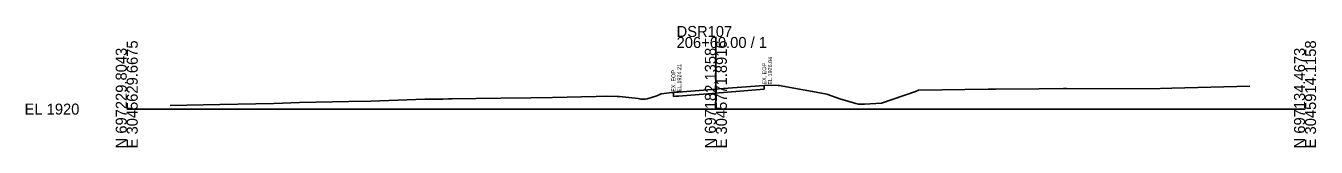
# Model space of a CAD drawing. Extents: x -26 to 19003, y -31 to 24541.
# Drawn here: x 1974.3 to 2302.8, y 13490.3 to 13521.2 of the extents above; entities that cross this region are included whole.
import ezdxf

# ---------------------------------------------------------------- set-up
doc = ezdxf.new("R2010")
doc.units = 0
for name, color, linetype in [('DESIGN - SHEET - Light Grid', 7, 'Continuous'), ('SURVEY - GROUND - Existing Pavement Layer', 7, 'Continuous'), ('SURVEY - GROUND - Existing Pavement Text', 7, 'Continuous'), ('SURVEY - GROUND - Top of Ground', 7, 'Continuous')]:
    doc.layers.add(name, color=color, linetype=linetype)

msp = doc.modelspace()

# ---------------------------------------------------------------- linework, layer by layer
at = {"layer": 'DESIGN - SHEET - Light Grid'}
for p, q in [((2150, 13500), (2150, 13518.36)), ((2000, 13500), (2150, 13500)), ((2150, 13500), (2300, 13500))]:
    msp.add_line(p, q, dxfattribs=at)
at = {"layer": 'SURVEY - GROUND - Existing Pavement Layer'}
for p, q in [((2162.31, 13506.04), (2162.31, 13505.04)), ((2139.18, 13503.21), (2139.18, 13504.21)), ((2139.18, 13503.21), (2139.79, 13503.28)), ((2139.79, 13503.28), (2140.48, 13503.33)), ((2140.48, 13503.33), (2150, 13504.06)), ((2150, 13504.06), (2150.8, 13504.12)), ((2150.8, 13504.12), (2151.91, 13504.21)), ((2151.91, 13504.21), (2162.31, 13505.04))]:
    msp.add_line(p, q, dxfattribs=at)
at = {"layer": 'SURVEY - GROUND - Top of Ground'}
msp.add_lwpolyline([(2011.04, 13500.9), (2023.69, 13501.15), (2037.46, 13501.45), (2043.96, 13501.71), (2056.55, 13501.93), (2062.17, 13502.05), (2075.92, 13502.53), (2078.22, 13502.52), (2080.59, 13502.57), (2081.9, 13502.59), (2082.83, 13502.61), (2088.95, 13502.7), (2095.26, 13502.79), (2102.92, 13502.88), (2108.41, 13502.94), (2119.49, 13503.2), (2122.24, 13503.29), (2124.9, 13503.25), (2125.48, 13503.25), (2130.21, 13502.67), (2130.91, 13502.52), (2132.01, 13502.56), (2132.49, 13502.6), (2134.96, 13503.34), (2136.11, 13503.88), (2138.14, 13504.1), (2139.18, 13504.21), (2139.79, 13504.28), (2140.48, 13504.33), (2150, 13505.06), (2150.8, 13505.12), (2151.91, 13505.21), (2162.31, 13506.04), (2163.39, 13506.12), (2165.87, 13506.05), (2166.18, 13506.04), (2167.08, 13505.85), (2176.48, 13504.12), (2178.26, 13503.78), (2181.58, 13502.63), (2185.59, 13501.41), (2186.3, 13501.22), (2187.87, 13501.28), (2192.14, 13501.54), (2200.85, 13504.48), (2201.57, 13504.79), (2219.31, 13505.06), (2221.25, 13505.1), (2232.24, 13505.19), (2238.53, 13505.24), (2239.31, 13505.26), (2260.2, 13505.2), (2266.11, 13505.35), (2285.98, 13505.81)], dxfattribs=at)

# ---------------------------------------------------------------- texts
at = {"layer": 'DESIGN - SHEET - Light Grid'}
for s, p in [('DSR107', (2140, 13518.36)), ('206+60.00 / 1', (2140, 13515.56)), ('EL 1920', (1974, 13498.6))]:
    msp.add_text(s, height=2.8, dxfattribs=at).set_placement(p)
for s, p in [('E 3045629.6675', (2002.8, 13490)), ('E 3045771.8916', (2152.8, 13490)), ('E 3045914.1158', (2302.8, 13490)), ('N 697229.8043', (2000, 13490)), ('N 697182.1358', (2150, 13490)), ('N 697134.4673', (2300, 13490))]:
    msp.add_text(s, height=2.8, rotation=90, dxfattribs=at).set_placement(p)
at = {"layer": 'SURVEY - GROUND - Existing Pavement Text'}
for s, p in [('EL.1926.04', (2164.31, 13506.24)), ('EX. EOP', (2139.68, 13504.41)), ('EL.1924.21', (2141.18, 13504.41)), ('EX. EOP', (2162.81, 13506.24))]:
    msp.add_text(s, height=1, rotation=90, dxfattribs=at).set_placement(p)

doc.saveas('drawing.dxf')
